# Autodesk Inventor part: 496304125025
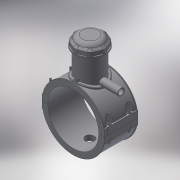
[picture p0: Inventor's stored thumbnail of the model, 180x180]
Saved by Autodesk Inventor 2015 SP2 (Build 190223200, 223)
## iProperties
Created: 2017-07
Part Number: 496304125025
Material: Generic
Description: PLASSON TAPPING SADDLE 125x25
Document SubType Name: Modeling
Designer: KIM
Mass: 854.057 g
Surface Area: 1820.49 cm^2
Volume: 854.057 cm^3
Density: 1 g/cm^3
Appearance: Default
Author: KIM
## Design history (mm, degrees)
derived "496304.ipt"
feature "Solid1::496304.ipt"
feature "Solid2::496304.ipt"
feature "Solid4::496304.ipt"
feature "Solid5::496304.ipt"
tag "TaggingFeature1"
body "Solid1"
body "Solid2"
other parameters: "d0" = 125, "d2" = 162, "d3" = 31.25, "d4" = 118, "d5" = 0, "d6" = 0.1, "d8" = 0, "d19" = 6, "d20" = 6, "d21" = 70.8, "d23" = 0, "d24" = 35.4, "d26" = 0, "d29" = 3, "d30" = 41.66667, "d31" = 6, "d32" = 0, "d33" = 0, "d34" = 0.6, "d40" = 78, "d41" = 75, "d43" = 0, "d45" = 0, "d47" = 145.8, "d70" = 15, "d72" = 0, "d73" = 6, "d75" = 5, "d76" = 0, "d77" = 6.25, "d78" = 92.5, "d79" = 15, "d80" = 47.2, "d82" = 5 deg, "d84" = 4, "d85" = 14, "d86" = 0, "d87" = 3, "d88" = 0, "d89" = 1, "d90" = 1, "d91" = 94.4, "d92" = 0, "d93" = 0.5, "d94" = 65.78947, "d96" = 153, "d97" = 2.36, "d98" = 0, "d102" = 1.25, "d120" = 140 deg, "d121" = 24.228, "d122" = 20 deg, "d126" = 0, "d143" = 128.75, "d145" = 19.23077, "d149" = 1.875, "d150" = 21.15385, "d153" = 118, "d154" = 0, "d156" = 75, "d157" = 160 deg, "d159" = 5, "d161" = 1.875, "d162" = 70.8, "d163" = 0, "d164" = 62.5, "d167" = 12.5, "d168" = 73.17073, "d170" = 3.375, "d172" = 0, "d173" = 1, "d175" = 62.5, "d176" = 20 deg, "d177" = 8.75, "d178" = 25, "d180" = 0, "d184" = 7, "d185" = 38.35, "d186" = 38.35, "d187" = 75, "d188" = 7.5, "d189" = 8.75, "d190" = 0, "d191" = 112.5, "d193" = 6.3, "d194" = 4.13, "d195" = 90 deg, "d197" = 0, "d199" = 0, "d200" = 12.5, "d202" = 0, "d203" = 114, "d204" = 71.25, "d205" = 52.5, "d206" = 63.75, "d207" = 85.5, "d208" = 88.92, "d209" = 106.02, "d210" = 64.5, "d211" = 75, "d213" = 3.15, "d216" = 0, "d217" = 12.5, "d218" = 12.5, "d219" = 2.5, "d222" = 125, "d224" = 0, "d230" = 5, "d233" = 6, "d236" = 81, "d237" = 35.4, "d238" = 6.02433, "d240" = 35.4, "d241" = 35.4, "d242" = 35.4, "d243" = 6, "d244" = 35.4, "d245" = 35.4, "d246" = 35.4, "d247" = 6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
